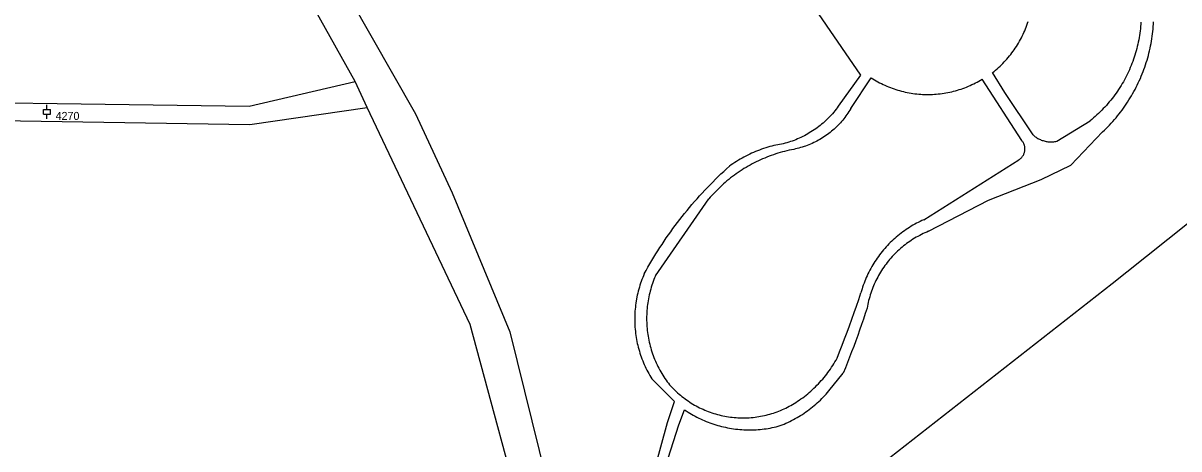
# Model space of a CAD drawing. Extents: x -733394 to -722299, y -1082822 to -1075049.
# Drawn here: x -730773.8 to -730528.3, y -1079594.6 to -1079504.1 of the extents above; entities that cross this region are included whole.
import ezdxf

# ---------------------------------------------------------------- set-up
doc = ezdxf.new("R2010")
doc.units = 0
for name, color, linetype in [('Hranice parcel', 7, 'Continuous'), ('Parcelní čísla', 7, 'Continuous'), ('Vnitřní kresba', 7, 'Continuous'), ('Značky kultur', 7, 'Continuous')]:
    doc.layers.add(name, color=color, linetype=linetype)

msp = doc.modelspace()

# ---------------------------------------------------------------- linework, layer by layer
at = {"layer": 'Hranice parcel'}
for p, q in [((-730714.03, -1079482.03), (-730690.45, -1079523.38)), ((-730703.31, -1079516.5), (-730711.57, -1079501.69)), ((-730700.7, -1079522.01), (-730703.31, -1079516.5))]:
    msp.add_line(p, q, dxfattribs=at)
for points in [[(-731412.96, -1079395.41), (-731354.96, -1079384.72), (-731307.56, -1079379.53), (-731248.71, -1079376.11), (-731194.41, -1079381.3), (-731137.42, -1079403.32), (-730968.61, -1079483.66), (-730937.54, -1079496.91), (-730818.76, -1079524.18), (-730725.69, -1079525.62), (-730700.7, -1079522.01)], [(-731034.49, -1079449.19), (-730967.59, -1079480.76), (-730936.25, -1079493.85), (-730817.68, -1079520.48), (-730725.81, -1079521.75), (-730703.31, -1079516.5)], [(-730435.57, -1079474.4), (-730435.73, -1079474.52), (-730471.81, -1079503.16), (-730509.38, -1079533.13), (-730539.38, -1079557.01), (-730542.5, -1079559.5), (-730605.96, -1079609.22), (-730651.92, -1079645.04)], [(-730718.98, -1079933.24), (-730709.14, -1079887.71), (-730675.98, -1079809.39), (-730665.33, -1079773.87), (-730661.93, -1079743.11), (-730661.58, -1079647.34), (-730666.2, -1079615.05), (-730678.85, -1079568.18), (-730700.7, -1079522.01)], [(-730690.45, -1079523.38), (-730682.7, -1079540.18), (-730670.42, -1079569.73), (-730657.94, -1079620.16), (-730651.92, -1079645.04)]]:
    msp.add_lwpolyline(points, dxfattribs=at)
at = {"layer": 'Vnitřní kresba'}
for p, q in [((-730615.11, -1079487.08), (-730595.93, -1079515.17)), ((-730595.93, -1079515.17), (-730600.64, -1079521.77)), ((-730598, -1079522.27), (-730593.65, -1079515.71)), ((-730561.66, -1079529.07), (-730570.06, -1079515.99)), ((-730565.29, -1079518.81), (-730567.87, -1079514.62)), ((-730559.28, -1079527.85), (-730565.29, -1079518.81)), ((-730554.24, -1079529.21), (-730547.15, -1079524.85)), ((-730551.22, -1079534.26), (-730544.5, -1079527.21)), ((-730582.48, -1079545.89), (-730562.32, -1079533.14)), ((-730557.55, -1079537.33), (-730551.22, -1079534.26)), ((-730568.71, -1079541.73), (-730557.55, -1079537.33)), ((-730639.51, -1079557.83), (-730628.15, -1079541.47)), ((-730581.49, -1079548.34), (-730568.71, -1079541.73)), ((-730635.44, -1079584.52), (-730640.25, -1079579.7)), ((-730602.65, -1079582.25), (-730599.61, -1079578.51)), ((-730636.93, -1079589.01), (-730635.44, -1079584.52)), ((-730634.49, -1079589.48), (-730633.29, -1079586.27)), ((-730641.3, -1079604.72), (-730636.93, -1079589.01)), ((-730639.38, -1079604.5), (-730634.49, -1079589.48))]:
    msp.add_line(p, q, dxfattribs=at)
for points in [[(-730567.87, -1079514.62), (-730567.54, -1079514.36), (-730567.22, -1079514.09), (-730566.9, -1079513.81), (-730566.59, -1079513.53), (-730566.28, -1079513.25), (-730565.98, -1079512.95), (-730565.68, -1079512.66), (-730565.39, -1079512.35), (-730565.1, -1079512.04), (-730564.82, -1079511.73), (-730564.55, -1079511.41), (-730564.28, -1079511.08), (-730564.02, -1079510.76), (-730563.77, -1079510.42), (-730563.52, -1079510.08), (-730563.27, -1079509.74), (-730563.04, -1079509.39), (-730562.81, -1079509.04), (-730562.58, -1079508.68), (-730562.37, -1079508.32), (-730562.16, -1079507.96), (-730561.95, -1079507.59), (-730561.76, -1079507.22), (-730561.57, -1079506.84), (-730561.39, -1079506.46), (-730561.21, -1079506.08), (-730561.04, -1079505.7), (-730560.88, -1079505.31), (-730560.73, -1079504.92), (-730560.58, -1079504.52), (-730560.44, -1079504.12), (-730560.31, -1079503.73)], [(-730536.36, -1079503.86), (-730536.39, -1079504.33), (-730536.43, -1079504.81), (-730536.48, -1079505.28), (-730536.53, -1079505.76), (-730536.59, -1079506.23), (-730536.66, -1079506.7), (-730536.74, -1079507.17), (-730536.83, -1079507.64), (-730536.92, -1079508.11), (-730537.02, -1079508.57), (-730537.13, -1079509.04), (-730537.24, -1079509.5), (-730537.36, -1079509.96), (-730537.49, -1079510.42), (-730537.63, -1079510.88), (-730537.78, -1079511.33), (-730537.93, -1079511.78), (-730538.09, -1079512.23), (-730538.26, -1079512.68), (-730538.44, -1079513.12), (-730538.62, -1079513.56), (-730538.81, -1079514), (-730539, -1079514.43), (-730539.21, -1079514.86), (-730539.42, -1079515.29), (-730539.64, -1079515.71), (-730539.86, -1079516.13), (-730540.09, -1079516.55), (-730540.33, -1079516.96), (-730540.58, -1079517.37), (-730540.83, -1079517.77), (-730541.09, -1079518.17), (-730541.35, -1079518.57), (-730541.62, -1079518.96), (-730541.9, -1079519.35), (-730542.19, -1079519.73), (-730542.48, -1079520.11), (-730542.77, -1079520.48), (-730543.08, -1079520.85), (-730543.38, -1079521.21), (-730543.7, -1079521.57), (-730544.02, -1079521.93), (-730544.35, -1079522.27), (-730544.68, -1079522.61), (-730545.01, -1079522.95), (-730545.36, -1079523.28), (-730545.71, -1079523.61), (-730546.06, -1079523.93), (-730546.42, -1079524.24), (-730546.78, -1079524.55), (-730547.15, -1079524.85)], [(-730544.5, -1079527.21), (-730544.12, -1079526.85), (-730543.75, -1079526.49), (-730543.39, -1079526.12), (-730543.03, -1079525.75), (-730542.68, -1079525.37), (-730542.33, -1079524.98), (-730541.99, -1079524.59), (-730541.65, -1079524.2), (-730541.32, -1079523.8), (-730541, -1079523.4), (-730540.68, -1079522.99), (-730540.37, -1079522.57), (-730540.06, -1079522.15), (-730539.76, -1079521.73), (-730539.47, -1079521.3), (-730539.19, -1079520.87), (-730538.91, -1079520.43), (-730538.63, -1079519.99), (-730538.37, -1079519.55), (-730538.11, -1079519.1), (-730537.85, -1079518.64), (-730537.61, -1079518.19), (-730537.37, -1079517.73), (-730537.14, -1079517.26), (-730536.91, -1079516.8), (-730536.7, -1079516.33), (-730536.48, -1079515.85), (-730536.28, -1079515.38), (-730536.09, -1079514.9), (-730535.9, -1079514.41), (-730535.72, -1079513.93), (-730535.54, -1079513.44), (-730535.38, -1079512.95), (-730535.22, -1079512.46), (-730535.06, -1079511.96), (-730534.92, -1079511.46), (-730534.78, -1079510.96), (-730534.65, -1079510.46), (-730534.53, -1079509.96), (-730534.42, -1079509.45), (-730534.31, -1079508.94), (-730534.21, -1079508.43), (-730534.12, -1079507.92), (-730534.04, -1079507.41), (-730533.96, -1079506.9), (-730533.9, -1079506.38), (-730533.84, -1079505.87), (-730533.78, -1079505.35), (-730533.74, -1079504.84), (-730533.7, -1079504.32), (-730533.67, -1079503.8)], [(-730593.65, -1079515.71), (-730593.3, -1079515.93), (-730592.95, -1079516.15), (-730592.59, -1079516.36), (-730592.23, -1079516.56), (-730591.86, -1079516.76), (-730591.49, -1079516.94), (-730591.12, -1079517.12), (-730590.74, -1079517.3), (-730590.36, -1079517.47), (-730589.98, -1079517.63), (-730589.59, -1079517.78), (-730589.21, -1079517.93), (-730588.81, -1079518.06), (-730588.42, -1079518.2), (-730588.02, -1079518.32), (-730587.63, -1079518.44), (-730587.23, -1079518.54), (-730586.82, -1079518.65), (-730586.42, -1079518.74), (-730586.01, -1079518.82), (-730585.61, -1079518.9), (-730585.2, -1079518.97), (-730584.79, -1079519.04), (-730584.38, -1079519.09), (-730583.97, -1079519.14), (-730583.55, -1079519.18), (-730583.14, -1079519.21), (-730582.73, -1079519.24), (-730582.31, -1079519.25), (-730581.9, -1079519.26), (-730581.48, -1079519.26), (-730581.07, -1079519.26), (-730580.65, -1079519.24), (-730580.24, -1079519.22), (-730579.82, -1079519.19), (-730579.41, -1079519.15), (-730579, -1079519.11), (-730578.59, -1079519.05), (-730578.18, -1079518.99), (-730577.77, -1079518.92), (-730577.36, -1079518.85), (-730576.95, -1079518.76), (-730576.55, -1079518.67), (-730576.15, -1079518.57), (-730575.75, -1079518.47), (-730575.35, -1079518.35), (-730574.95, -1079518.23), (-730574.56, -1079518.1), (-730574.17, -1079517.96), (-730573.78, -1079517.82), (-730573.39, -1079517.67), (-730573.01, -1079517.51), (-730572.63, -1079517.34), (-730572.25, -1079517.17), (-730571.88, -1079516.99), (-730571.51, -1079516.81), (-730571.14, -1079516.61), (-730570.78, -1079516.41), (-730570.42, -1079516.2), (-730570.06, -1079515.99)], [(-730600.64, -1079521.77), (-730600.88, -1079522.09), (-730601.12, -1079522.41), (-730601.37, -1079522.73), (-730601.62, -1079523.04), (-730601.89, -1079523.34), (-730602.15, -1079523.64), (-730602.43, -1079523.94), (-730602.7, -1079524.23), (-730602.99, -1079524.51), (-730603.28, -1079524.79), (-730603.57, -1079525.06), (-730603.87, -1079525.33), (-730604.18, -1079525.59), (-730604.49, -1079525.84), (-730604.81, -1079526.09), (-730605.13, -1079526.33), (-730605.45, -1079526.56), (-730605.78, -1079526.79), (-730606.11, -1079527.02), (-730606.45, -1079527.23), (-730606.8, -1079527.44), (-730607.14, -1079527.65), (-730607.49, -1079527.84), (-730607.85, -1079528.03), (-730608.21, -1079528.21), (-730608.57, -1079528.39), (-730608.93, -1079528.55), (-730609.3, -1079528.71), (-730609.67, -1079528.87), (-730610.04, -1079529.01), (-730610.42, -1079529.15), (-730610.8, -1079529.28), (-730611.18, -1079529.41), (-730611.57, -1079529.52), (-730611.95, -1079529.63), (-730612.34, -1079529.73), (-730612.73, -1079529.82), (-730613.12, -1079529.91), (-730613.52, -1079529.99), (-730613.91, -1079530.06), (-730614.31, -1079530.12)], [(-730598, -1079522.27), (-730598.19, -1079522.59), (-730598.39, -1079522.91), (-730598.6, -1079523.22), (-730598.81, -1079523.53), (-730599.02, -1079523.83), (-730599.25, -1079524.13), (-730599.48, -1079524.43), (-730599.71, -1079524.72), (-730599.95, -1079525), (-730600.2, -1079525.28), (-730600.45, -1079525.56), (-730600.71, -1079525.83), (-730600.98, -1079526.09), (-730601.25, -1079526.35), (-730601.52, -1079526.6), (-730601.8, -1079526.85), (-730602.09, -1079527.09), (-730602.38, -1079527.33), (-730602.67, -1079527.56), (-730602.97, -1079527.78), (-730603.28, -1079528), (-730603.58, -1079528.21), (-730603.9, -1079528.42), (-730604.21, -1079528.61), (-730604.54, -1079528.81), (-730604.86, -1079528.99), (-730605.19, -1079529.17), (-730605.52, -1079529.34), (-730605.86, -1079529.5), (-730606.2, -1079529.66), (-730606.54, -1079529.81), (-730606.88, -1079529.96), (-730607.23, -1079530.09), (-730607.58, -1079530.22), (-730607.93, -1079530.34), (-730608.29, -1079530.46), (-730608.65, -1079530.56), (-730609.01, -1079530.67), (-730609.37, -1079530.76), (-730609.73, -1079530.84), (-730610.1, -1079530.92)], [(-730559.28, -1079527.85), (-730559.12, -1079527.99), (-730558.96, -1079528.12), (-730558.79, -1079528.24), (-730558.62, -1079528.36), (-730558.45, -1079528.47), (-730558.27, -1079528.58), (-730558.08, -1079528.68), (-730557.9, -1079528.77), (-730557.71, -1079528.86), (-730557.52, -1079528.94), (-730557.32, -1079529.01), (-730557.12, -1079529.07), (-730556.92, -1079529.13), (-730556.72, -1079529.18), (-730556.52, -1079529.23), (-730556.31, -1079529.26), (-730556.1, -1079529.29), (-730555.9, -1079529.31), (-730555.69, -1079529.32), (-730555.48, -1079529.33), (-730555.27, -1079529.33), (-730555.07, -1079529.32), (-730554.86, -1079529.3), (-730554.65, -1079529.28), (-730554.45, -1079529.25), (-730554.24, -1079529.21)], [(-730610.1, -1079530.92), (-730610.59, -1079531.02), (-730611.07, -1079531.12), (-730611.56, -1079531.23), (-730612.04, -1079531.35), (-730612.52, -1079531.48), (-730612.99, -1079531.61), (-730613.47, -1079531.75), (-730613.94, -1079531.9), (-730614.41, -1079532.06), (-730614.88, -1079532.22), (-730615.35, -1079532.39), (-730615.81, -1079532.57), (-730616.27, -1079532.76), (-730616.72, -1079532.95), (-730617.18, -1079533.15), (-730617.63, -1079533.36), (-730618.07, -1079533.58), (-730618.52, -1079533.8), (-730618.96, -1079534.03), (-730619.39, -1079534.27), (-730619.82, -1079534.51), (-730620.25, -1079534.76), (-730620.68, -1079535.02), (-730621.1, -1079535.28), (-730621.51, -1079535.55), (-730621.92, -1079535.83), (-730622.33, -1079536.11), (-730622.73, -1079536.4), (-730623.13, -1079536.7), (-730623.52, -1079537), (-730623.91, -1079537.31), (-730624.29, -1079537.62), (-730624.67, -1079537.94), (-730625.04, -1079538.27), (-730625.41, -1079538.6), (-730625.77, -1079538.94), (-730626.13, -1079539.29), (-730626.48, -1079539.64), (-730626.83, -1079539.99), (-730627.17, -1079540.35), (-730627.5, -1079540.72), (-730627.83, -1079541.09), (-730628.15, -1079541.47)], [(-730614.31, -1079530.12), (-730614.75, -1079530.23), (-730615.19, -1079530.35), (-730615.63, -1079530.48), (-730616.07, -1079530.61), (-730616.5, -1079530.76), (-730616.94, -1079530.91), (-730617.36, -1079531.06), (-730617.79, -1079531.22), (-730618.22, -1079531.4), (-730618.64, -1079531.57), (-730619.05, -1079531.76), (-730619.47, -1079531.95), (-730619.88, -1079532.15), (-730620.29, -1079532.35), (-730620.69, -1079532.56), (-730621.09, -1079532.78), (-730621.49, -1079533.01), (-730621.88, -1079533.24), (-730622.27, -1079533.48), (-730622.66, -1079533.73), (-730623.04, -1079533.98), (-730623.42, -1079534.24), (-730623.79, -1079534.5)], [(-730562.32, -1079533.14), (-730562.2, -1079533.06), (-730562.08, -1079532.98), (-730561.97, -1079532.9), (-730561.86, -1079532.8), (-730561.76, -1079532.71), (-730561.66, -1079532.6), (-730561.57, -1079532.49), (-730561.48, -1079532.38), (-730561.4, -1079532.26), (-730561.33, -1079532.14), (-730561.26, -1079532.01), (-730561.2, -1079531.88), (-730561.15, -1079531.75), (-730561.1, -1079531.61), (-730561.07, -1079531.47), (-730561.04, -1079531.33), (-730561.01, -1079531.19), (-730561, -1079531.05), (-730560.99, -1079530.91), (-730560.99, -1079530.76), (-730561, -1079530.62), (-730561.01, -1079530.48), (-730561.04, -1079530.34), (-730561.07, -1079530.2), (-730561.1, -1079530.06), (-730561.15, -1079529.92), (-730561.2, -1079529.79), (-730561.26, -1079529.66), (-730561.33, -1079529.54), (-730561.4, -1079529.41), (-730561.48, -1079529.29), (-730561.57, -1079529.18), (-730561.66, -1079529.07)], [(-730641.87, -1079557.38), (-730641.48, -1079556.67), (-730641.08, -1079555.96), (-730640.67, -1079555.25), (-730640.26, -1079554.55), (-730639.84, -1079553.86), (-730639.41, -1079553.16), (-730638.98, -1079552.47), (-730638.54, -1079551.79), (-730638.09, -1079551.11), (-730637.64, -1079550.43), (-730637.18, -1079549.76), (-730636.72, -1079549.09), (-730636.24, -1079548.43), (-730635.77, -1079547.77), (-730635.28, -1079547.11), (-730634.79, -1079546.46), (-730634.3, -1079545.82), (-730633.8, -1079545.18), (-730633.29, -1079544.54), (-730632.78, -1079543.91), (-730632.26, -1079543.28), (-730631.73, -1079542.66), (-730631.2, -1079542.04), (-730630.66, -1079541.43), (-730630.12, -1079540.82), (-730629.57, -1079540.22), (-730629.02, -1079539.63), (-730628.46, -1079539.04), (-730627.89, -1079538.45), (-730627.32, -1079537.87), (-730626.75, -1079537.29), (-730626.17, -1079536.72), (-730625.58, -1079536.16), (-730624.99, -1079535.6), (-730624.39, -1079535.05), (-730623.79, -1079534.5)], [(-730582.48, -1079545.89), (-730582.87, -1079546.07), (-730583.27, -1079546.25), (-730583.65, -1079546.44), (-730584.04, -1079546.64), (-730584.42, -1079546.85), (-730584.79, -1079547.06), (-730585.17, -1079547.28), (-730585.53, -1079547.51), (-730585.9, -1079547.74), (-730586.26, -1079547.98), (-730586.61, -1079548.23), (-730586.97, -1079548.48), (-730587.31, -1079548.74), (-730587.65, -1079549), (-730587.99, -1079549.28), (-730588.32, -1079549.55), (-730588.65, -1079549.84), (-730588.97, -1079550.13), (-730589.29, -1079550.42), (-730589.6, -1079550.72), (-730589.9, -1079551.03), (-730590.2, -1079551.34), (-730590.49, -1079551.66), (-730590.78, -1079551.98), (-730591.06, -1079552.31), (-730591.34, -1079552.64), (-730591.61, -1079552.98), (-730591.87, -1079553.32), (-730592.13, -1079553.67), (-730592.38, -1079554.02), (-730592.63, -1079554.38), (-730592.86, -1079554.74), (-730593.1, -1079555.1), (-730593.32, -1079555.48), (-730593.54, -1079555.85), (-730593.75, -1079556.23), (-730593.95, -1079556.61), (-730594.15, -1079556.99), (-730594.34, -1079557.38), (-730594.52, -1079557.77), (-730594.7, -1079558.17), (-730594.87, -1079558.57), (-730595.03, -1079558.97), (-730595.18, -1079559.37), (-730595.33, -1079559.78), (-730595.47, -1079560.19), (-730595.6, -1079560.6), (-730595.72, -1079561.01), (-730595.84, -1079561.43)], [(-730581.49, -1079548.34), (-730581.87, -1079548.5), (-730582.25, -1079548.67), (-730582.62, -1079548.84), (-730582.99, -1079549.02), (-730583.35, -1079549.21), (-730583.72, -1079549.41), (-730584.08, -1079549.61), (-730584.43, -1079549.82), (-730584.78, -1079550.03), (-730585.13, -1079550.26), (-730585.47, -1079550.48), (-730585.81, -1079550.72), (-730586.14, -1079550.96), (-730586.47, -1079551.21), (-730586.79, -1079551.46), (-730587.11, -1079551.73), (-730587.43, -1079551.99), (-730587.73, -1079552.27), (-730588.04, -1079552.54), (-730588.34, -1079552.83), (-730588.63, -1079553.12), (-730588.92, -1079553.41), (-730589.2, -1079553.72), (-730589.47, -1079554.02), (-730589.74, -1079554.33), (-730590, -1079554.65), (-730590.26, -1079554.97), (-730590.51, -1079555.3), (-730590.76, -1079555.63), (-730590.99, -1079555.97), (-730591.23, -1079556.31), (-730591.45, -1079556.65), (-730591.67, -1079557), (-730591.88, -1079557.35), (-730592.08, -1079557.71), (-730592.28, -1079558.07), (-730592.47, -1079558.44), (-730592.66, -1079558.81), (-730592.83, -1079559.18), (-730593, -1079559.55), (-730593.17, -1079559.93), (-730593.32, -1079560.31), (-730593.47, -1079560.7), (-730593.61, -1079561.08), (-730593.74, -1079561.48), (-730593.87, -1079561.87), (-730593.98, -1079562.26), (-730594.09, -1079562.66), (-730594.2, -1079563.06), (-730594.29, -1079563.46), (-730594.38, -1079563.86), (-730594.46, -1079564.26), (-730594.53, -1079564.67)], [(-730641.87, -1079557.38), (-730642.04, -1079557.78), (-730642.2, -1079558.18), (-730642.36, -1079558.58), (-730642.51, -1079558.98), (-730642.65, -1079559.39), (-730642.78, -1079559.8), (-730642.91, -1079560.21), (-730643.03, -1079560.63), (-730643.14, -1079561.04), (-730643.24, -1079561.46), (-730643.34, -1079561.88), (-730643.43, -1079562.3), (-730643.51, -1079562.73), (-730643.59, -1079563.15), (-730643.65, -1079563.58), (-730643.71, -1079564.01), (-730643.76, -1079564.44), (-730643.8, -1079564.86), (-730643.84, -1079565.29), (-730643.86, -1079565.72), (-730643.88, -1079566.16), (-730643.9, -1079566.59), (-730643.9, -1079567.02), (-730643.9, -1079567.45), (-730643.88, -1079567.88), (-730643.86, -1079568.31), (-730643.84, -1079568.74), (-730643.8, -1079569.17), (-730643.76, -1079569.6), (-730643.71, -1079570.03), (-730643.65, -1079570.46), (-730643.58, -1079570.88), (-730643.51, -1079571.31), (-730643.43, -1079571.73), (-730643.34, -1079572.15), (-730643.24, -1079572.57), (-730643.14, -1079572.99), (-730643.03, -1079573.41), (-730642.91, -1079573.82), (-730642.78, -1079574.24), (-730642.65, -1079574.65), (-730642.51, -1079575.05), (-730642.36, -1079575.46), (-730642.2, -1079575.86), (-730642.04, -1079576.26), (-730641.87, -1079576.66), (-730641.69, -1079577.05), (-730641.5, -1079577.44), (-730641.31, -1079577.82), (-730641.11, -1079578.21), (-730640.91, -1079578.59), (-730640.7, -1079578.96), (-730640.48, -1079579.33), (-730640.25, -1079579.7)], [(-730639.51, -1079557.83), (-730639.67, -1079558.22), (-730639.83, -1079558.61), (-730639.98, -1079559.01), (-730640.12, -1079559.41), (-730640.25, -1079559.81), (-730640.38, -1079560.21), (-730640.5, -1079560.62), (-730640.61, -1079561.03), (-730640.71, -1079561.43), (-730640.81, -1079561.85), (-730640.9, -1079562.26), (-730640.98, -1079562.67), (-730641.05, -1079563.09), (-730641.12, -1079563.51), (-730641.18, -1079563.93), (-730641.23, -1079564.35), (-730641.27, -1079564.77), (-730641.31, -1079565.19), (-730641.33, -1079565.61), (-730641.35, -1079566.03), (-730641.36, -1079566.46), (-730641.37, -1079566.88), (-730641.36, -1079567.3), (-730641.35, -1079567.72), (-730641.33, -1079568.15), (-730641.3, -1079568.57), (-730641.27, -1079568.99), (-730641.22, -1079569.41), (-730641.17, -1079569.83), (-730641.11, -1079570.25), (-730641.05, -1079570.66), (-730640.97, -1079571.08), (-730640.89, -1079571.5), (-730640.8, -1079571.91), (-730640.71, -1079572.32), (-730640.6, -1079572.73), (-730640.49, -1079573.14), (-730640.37, -1079573.54), (-730640.24, -1079573.95), (-730640.11, -1079574.35), (-730639.97, -1079574.74), (-730639.82, -1079575.14), (-730639.66, -1079575.53), (-730639.5, -1079575.92), (-730639.33, -1079576.31), (-730639.15, -1079576.69), (-730638.96, -1079577.07), (-730638.77, -1079577.45), (-730638.57, -1079577.82), (-730638.36, -1079578.19), (-730638.15, -1079578.56), (-730637.93, -1079578.92), (-730637.71, -1079579.27), (-730637.47, -1079579.63), (-730637.23, -1079579.98), (-730636.99, -1079580.32)], [(-730600.9, -1079575.33), (-730600.36, -1079573.95), (-730599.83, -1079572.57), (-730599.31, -1079571.19), (-730598.79, -1079569.8), (-730598.28, -1079568.41), (-730597.78, -1079567.02), (-730597.28, -1079565.63), (-730596.79, -1079564.23), (-730596.31, -1079562.83), (-730595.84, -1079561.43)], [(-730594.53, -1079564.67), (-730594.92, -1079565.84), (-730595.31, -1079567), (-730595.71, -1079568.16), (-730596.12, -1079569.32), (-730596.53, -1079570.48), (-730596.95, -1079571.63), (-730597.38, -1079572.79), (-730597.81, -1079573.94), (-730598.25, -1079575.08), (-730598.7, -1079576.23), (-730599.15, -1079577.37), (-730599.61, -1079578.51)], [(-730609.68, -1079584.71), (-730609.31, -1079584.47), (-730608.93, -1079584.22), (-730608.57, -1079583.96), (-730608.21, -1079583.7), (-730607.85, -1079583.43), (-730607.49, -1079583.15), (-730607.15, -1079582.87), (-730606.8, -1079582.58), (-730606.47, -1079582.29), (-730606.13, -1079581.99), (-730605.81, -1079581.68), (-730605.48, -1079581.37), (-730605.17, -1079581.06), (-730604.85, -1079580.73), (-730604.55, -1079580.41), (-730604.25, -1079580.07), (-730603.95, -1079579.74), (-730603.67, -1079579.4), (-730603.38, -1079579.05), (-730603.11, -1079578.7), (-730602.84, -1079578.34), (-730602.57, -1079577.98), (-730602.31, -1079577.61), (-730602.06, -1079577.24), (-730601.82, -1079576.87), (-730601.58, -1079576.49), (-730601.35, -1079576.11), (-730601.12, -1079575.72), (-730600.9, -1079575.33)], [(-730636.99, -1079580.32), (-730636.73, -1079580.63), (-730636.47, -1079580.94), (-730636.2, -1079581.24), (-730635.93, -1079581.53), (-730635.64, -1079581.82), (-730635.36, -1079582.11), (-730635.07, -1079582.39), (-730634.77, -1079582.66), (-730634.47, -1079582.93), (-730634.16, -1079583.19), (-730633.85, -1079583.44), (-730633.53, -1079583.69), (-730633.21, -1079583.94), (-730632.88, -1079584.17), (-730632.55, -1079584.4), (-730632.21, -1079584.63), (-730631.87, -1079584.84), (-730631.53, -1079585.05), (-730631.18, -1079585.26), (-730630.83, -1079585.45), (-730630.47, -1079585.64), (-730630.11, -1079585.83), (-730629.75, -1079586), (-730629.38, -1079586.17), (-730629.01, -1079586.33), (-730628.64, -1079586.49), (-730628.26, -1079586.64), (-730627.88, -1079586.78), (-730627.5, -1079586.91), (-730627.12, -1079587.03), (-730626.73, -1079587.15), (-730626.34, -1079587.26), (-730625.95, -1079587.36), (-730625.56, -1079587.46), (-730625.17, -1079587.55), (-730624.77, -1079587.62), (-730624.37, -1079587.7), (-730623.97, -1079587.76), (-730623.57, -1079587.82), (-730623.17, -1079587.86), (-730622.77, -1079587.91), (-730622.37, -1079587.94), (-730621.97, -1079587.96), (-730621.56, -1079587.98), (-730621.16, -1079587.99), (-730620.76, -1079587.99), (-730620.35, -1079587.99), (-730619.95, -1079587.97), (-730619.55, -1079587.95), (-730619.14, -1079587.92), (-730618.74, -1079587.88), (-730618.34, -1079587.84), (-730617.94, -1079587.78), (-730617.54, -1079587.72), (-730617.14, -1079587.65), (-730616.75, -1079587.58), (-730616.35, -1079587.49), (-730615.96, -1079587.4), (-730615.57, -1079587.3), (-730615.18, -1079587.19), (-730614.79, -1079587.08), (-730614.41, -1079586.96), (-730614.03, -1079586.83), (-730613.65, -1079586.69), (-730613.27, -1079586.55), (-730612.89, -1079586.39), (-730612.52, -1079586.24), (-730612.16, -1079586.07), (-730611.79, -1079585.9), (-730611.43, -1079585.72), (-730611.07, -1079585.53), (-730610.72, -1079585.33), (-730610.37, -1079585.13), (-730610.02, -1079584.93), (-730609.68, -1079584.71)], [(-730613.42, -1079589.78), (-730613, -1079589.63), (-730612.59, -1079589.47), (-730612.18, -1079589.3), (-730611.77, -1079589.13), (-730611.37, -1079588.95), (-730610.97, -1079588.76), (-730610.57, -1079588.56), (-730610.18, -1079588.36), (-730609.78, -1079588.15), (-730609.4, -1079587.93), (-730609.02, -1079587.71), (-730608.64, -1079587.48), (-730608.26, -1079587.24), (-730607.89, -1079586.99), (-730607.53, -1079586.74), (-730607.17, -1079586.49), (-730606.81, -1079586.22), (-730606.46, -1079585.95), (-730606.11, -1079585.68), (-730605.77, -1079585.39), (-730605.43, -1079585.1), (-730605.1, -1079584.81), (-730604.78, -1079584.51), (-730604.45, -1079584.2), (-730604.14, -1079583.89), (-730603.83, -1079583.57), (-730603.53, -1079583.25), (-730603.23, -1079582.92), (-730602.94, -1079582.59), (-730602.65, -1079582.25)], [(-730633.29, -1079586.27), (-730632.93, -1079586.51), (-730632.57, -1079586.75), (-730632.2, -1079586.98), (-730631.83, -1079587.2), (-730631.45, -1079587.41), (-730631.07, -1079587.62), (-730630.69, -1079587.82), (-730630.3, -1079588.02), (-730629.91, -1079588.21), (-730629.52, -1079588.39), (-730629.12, -1079588.56), (-730628.72, -1079588.73), (-730628.32, -1079588.89), (-730627.91, -1079589.04), (-730627.5, -1079589.19), (-730627.09, -1079589.33), (-730626.68, -1079589.46), (-730626.27, -1079589.58), (-730625.85, -1079589.7), (-730625.43, -1079589.81), (-730625.01, -1079589.91), (-730624.59, -1079590), (-730624.16, -1079590.09), (-730623.73, -1079590.17), (-730623.31, -1079590.24), (-730622.88, -1079590.31), (-730622.45, -1079590.36), (-730622.02, -1079590.41), (-730621.59, -1079590.45), (-730621.15, -1079590.49), (-730620.72, -1079590.51), (-730620.29, -1079590.53), (-730619.86, -1079590.54), (-730619.42, -1079590.54), (-730618.99, -1079590.54), (-730618.56, -1079590.53), (-730618.12, -1079590.51), (-730617.69, -1079590.48), (-730617.26, -1079590.44), (-730616.83, -1079590.4), (-730616.4, -1079590.35), (-730615.97, -1079590.29), (-730615.54, -1079590.22), (-730615.11, -1079590.15), (-730614.69, -1079590.07), (-730614.26, -1079589.98), (-730613.84, -1079589.88), (-730613.42, -1079589.78)]]:
    msp.add_lwpolyline(points, dxfattribs=at)
at = {"layer": 'Značky kultur'}
for p, q in [((-730769.51, -1079522.43), (-730768.01, -1079522.43)), ((-730769.51, -1079523.43), (-730769.51, -1079522.43)), ((-730769.51, -1079523.43), (-730768.01, -1079523.43)), ((-730768.76, -1079522.43), (-730768.76, -1079521.43)), ((-730768.76, -1079524.43), (-730768.76, -1079523.43)), ((-730768.01, -1079523.43), (-730768.01, -1079522.43))]:
    msp.add_line(p, q, dxfattribs=at)

# ---------------------------------------------------------------- texts
at = {"layer": 'Parcelní čísla'}
msp.add_text('4270', height=1.7, dxfattribs=at).set_placement((-730766.92, -1079524.67))

doc.saveas('drawing.dxf')
